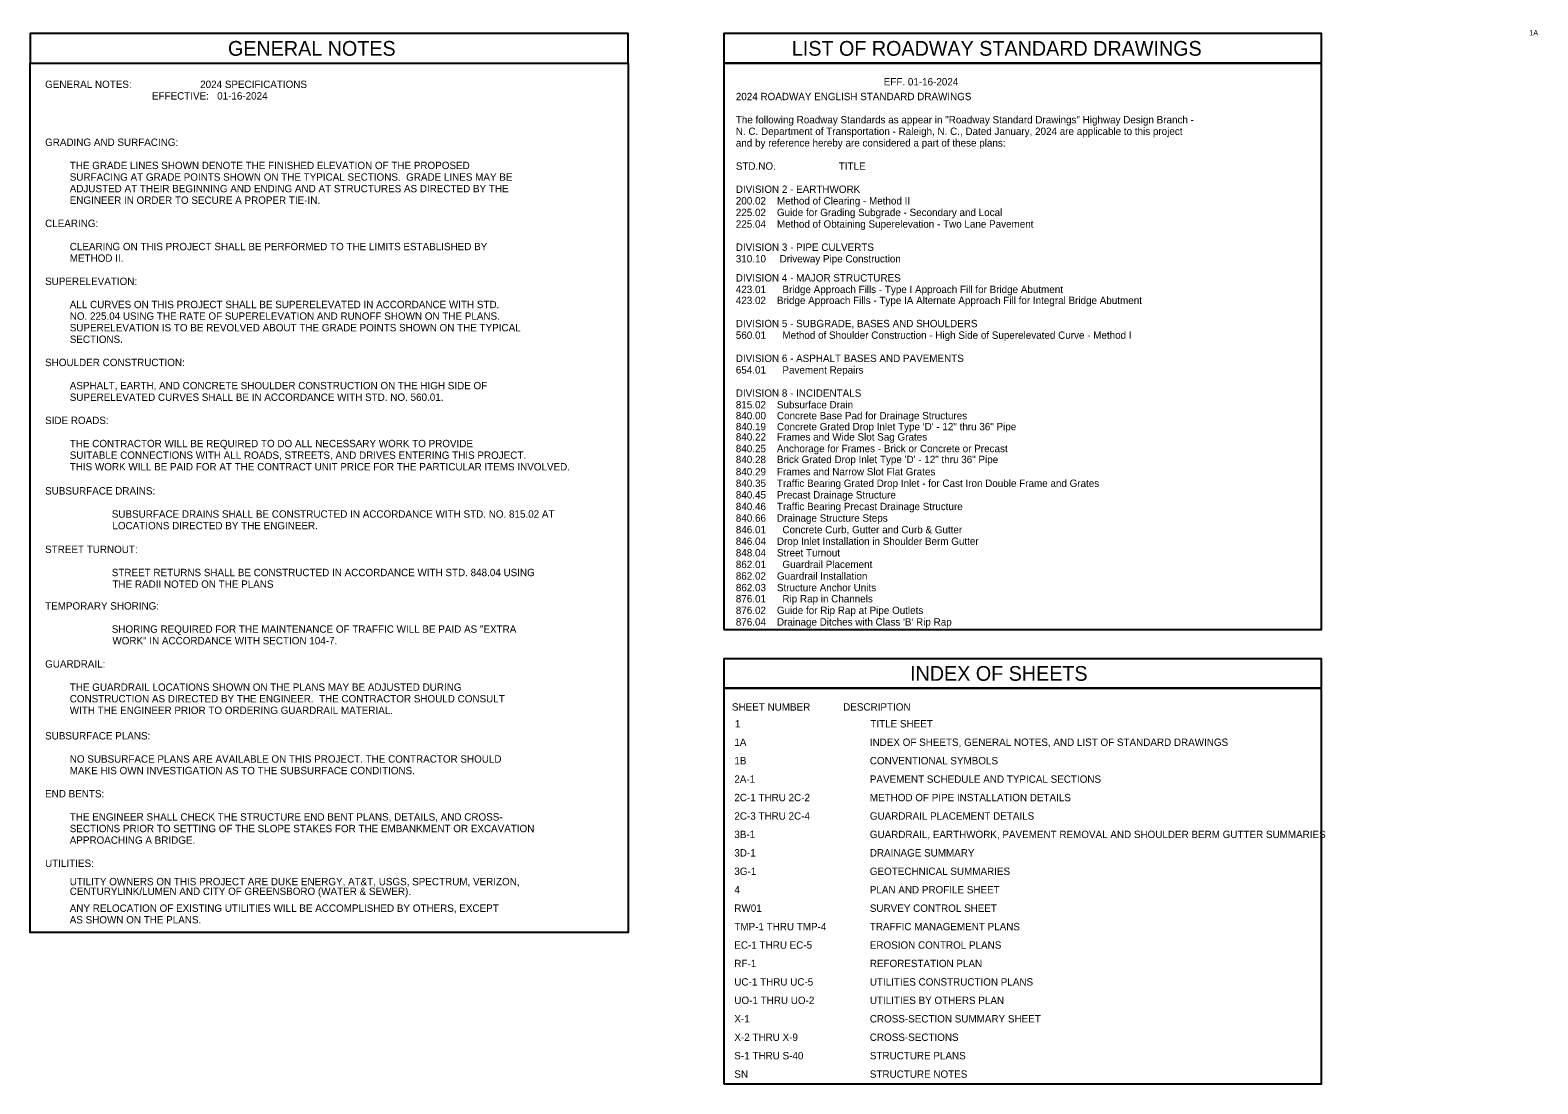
# Model space of a CAD drawing. Extents: x 1364250 to 1365681, y 623147 to 624147.
import ezdxf

# ---------------------------------------------------------------- set-up
doc = ezdxf.new("R2010")
doc.units = 0
for name, color, linetype in [('Old_Level_1', 7, 'Continuous'), ('Old_Level_40', 7, 'Continuous'), ('Old_Level_44', 7, 'Continuous')]:
    doc.layers.add(name, color=color, linetype=linetype)

msp = doc.modelspace()

# ---------------------------------------------------------------- linework, layer by layer
at = {"layer": 'Old_Level_1'}
for points in [[(1364249.5, 624116.2), (1364817.1, 624116.2), (1364817.1, 623290.9), (1364249.5, 623290.9)], [(1364907.9, 623578.6), (1365475.5, 623578.6), (1365475.5, 624116.2), (1364907.9, 624116.2)], [(1364907.9, 623147.3), (1365475.5, 623147.3), (1365475.5, 623522.9), (1364907.9, 623522.9)]]:
    msp.add_lwpolyline(points, close=True, dxfattribs=at)
at = {"layer": 'Old_Level_40'}
for points in [[(1364249.5, 624116.2), (1364817.1, 624116.2), (1364817.1, 624144.2), (1364249.5, 624144.2)], [(1364907.9, 624116.2), (1365475.5, 624116.2), (1365475.5, 624144.2), (1364907.9, 624144.2)], [(1364907.9, 623522.9), (1365475.5, 623522.9), (1365475.5, 623550.9), (1364907.9, 623550.9)]]:
    msp.add_lwpolyline(points, close=True, dxfattribs=at)

# ---------------------------------------------------------------- texts
at = {"layer": 'Old_Level_1'}
for s, p in [('                                                      EFF. 01-16-2024', (1364919.4, 624095)), ('GENERAL NOTES:                         2024 SPECIFICATIONS', (1364263.7, 624092.6)), ('GENERAL NOTES:                         2024 SPECIFICATIONS', (1364263.7, 624092.6)), ('                                       EFFECTIVE:   01-16-2024', (1364263.7, 624081.6)), ('2024 ROADWAY ENGLISH STANDARD DRAWINGS', (1364919.4, 624081)), ('The following Roadway Standards as appear in "Roadway Standard Drawings" Highway Design Branch -', (1364919.4, 624059)), ('GRADING AND SURFACING:  ', (1364263.7, 624037.6)), ('and by reference hereby are considered a part of these plans:', (1364919.4, 624037)), ('N. C. Department of Transportation - Raleigh, N. C., Dated January, 2024 are applicable to this project', (1364919.4, 624048)), ('         THE GRADE LINES SHOWN DENOTE THE FINISHED ELEVATION OF THE PROPOSED ', (1364263.7, 624015.6)), ('STD.NO.                       TITLE', (1364919.4, 624015)), ('         SURFACING AT GRADE POINTS SHOWN ON THE TYPICAL SECTIONS.  GRADE LINES MAY BE ', (1364263.7, 624004.6)), ('         ADJUSTED AT THEIR BEGINNING AND ENDING AND AT STRUCTURES AS DIRECTED BY THE ', (1364263.7, 623993.6)), ('         ENGINEER IN ORDER TO SECURE A PROPER TIE-IN.  ', (1364263.7, 623982.6)), ('200.02    Method of Clearing - Method II', (1364919.4, 623982)), ('DIVISION 2 - EARTHWORK', (1364919.4, 623993)), ('225.02    Guide for Grading Subgrade - Secondary and Local', (1364919.4, 623971)), ('CLEARING:  ', (1364263.7, 623960.6)), ('225.04    Method of Obtaining Superelevation - Two Lane Pavement', (1364919.4, 623960)), ('         CLEARING ON THIS PROJECT SHALL BE PERFORMED TO THE LIMITS ESTABLISHED BY ', (1364263.7, 623938.6)), ('DIVISION 3 - PIPE CULVERTS', (1364919.4, 623938)), ('         METHOD II.', (1364263.7, 623927.6)), ('310.10     Driveway Pipe Construction', (1364919.4, 623927)), ('DIVISION 4 - MAJOR STRUCTURES', (1364919.4, 623908.9)), ('SUPERELEVATION:  ', (1364263.7, 623905.6)), ('423.01      Bridge Approach Fills - Type I Approach Fill for Bridge Abutment', (1364919.4, 623897.9)), ('         ALL CURVES ON THIS PROJECT SHALL BE SUPERELEVATED IN ACCORDANCE WITH STD. ', (1364263.7, 623883.6)), ('423.02    Bridge Approach Fills - Type IA Alternate Approach Fill for Integral Bridge Abutment', (1364919.4, 623887.5)), ('         NO. 225.04 USING THE RATE OF SUPERELEVATION AND RUNOFF SHOWN ON THE PLANS.', (1364263.7, 623872.6)), ('DIVISION 5 - SUBGRADE, BASES AND SHOULDERS', (1364919.4, 623865.5)), ('         SUPERELEVATION IS TO BE REVOLVED ABOUT THE GRADE POINTS SHOWN ON THE TYPICAL ', (1364263.7, 623861.6)), ('560.01      Method of Shoulder Construction - High Side of Superelevated Curve - Method I', (1364919.4, 623854.5)), ('         SECTIONS.  ', (1364263.7, 623850.6)), ('SHOULDER CONSTRUCTION:  ', (1364263.7, 623828.6)), ('DIVISION 6 - ASPHALT BASES AND PAVEMENTS', (1364919.4, 623832.5)), ('654.01      Pavement Repairs', (1364919.4, 623821.5)), ('         ASPHALT, EARTH, AND CONCRETE SHOULDER CONSTRUCTION ON THE HIGH SIDE OF', (1364263.7, 623806.6)), ('         SUPERELEVATED CURVES SHALL BE IN ACCORDANCE WITH STD. NO. 560.01.', (1364263.7, 623795.6)), ('DIVISION 8 - INCIDENTALS', (1364919.4, 623799.5)), ('815.02    Subsurface Drain', (1364919.4, 623788.5)), ('SIDE ROADS:', (1364263.7, 623773.6)), ('840.00    Concrete Base Pad for Drainage Structures', (1364919.4, 623778.1)), ('840.19    Concrete Grated Drop Inlet Type \'D\' - 12" thru 36" Pipe', (1364919.4, 623767.7)), ('         THE CONTRACTOR WILL BE REQUIRED TO DO ALL NECESSARY WORK TO PROVIDE ', (1364263.7, 623751.6)), ('840.22    Frames and Wide Slot Sag Grates', (1364919.4, 623757.9)), ('         SUITABLE CONNECTIONS WITH ALL ROADS, STREETS, AND DRIVES ENTERING THIS PROJECT.', (1364263.7, 623740.6)), ('840.25    Anchorage for Frames - Brick or Concrete or Precast', (1364919.4, 623746.9)), ('840.28    Brick Grated Drop Inlet Type \'D\' - 12" thru 36" Pipe', (1364919.4, 623736.5)), ('         THIS WORK WILL BE PAID FOR AT THE CONTRACT UNIT PRICE FOR THE PARTICULAR ITEMS INVOLVED.', (1364263.7, 623729.6)), ('840.29    Frames and Narrow Slot Flat Grates', (1364919.4, 623724.9)), ('840.35    Traffic Bearing Grated Drop Inlet - for Cast Iron Double Frame and Grates', (1364919.4, 623713.9)), ('SUBSURFACE DRAINS:', (1364263.7, 623706.7)), ('840.45    Precast Drainage Structure', (1364919.4, 623702.9)), ('SUBSURFACE DRAINS SHALL BE CONSTRUCTED IN ACCORDANCE WITH STD. NO. 815.02 AT', (1364327, 623684.7)), ('840.46    Traffic Bearing Precast Drainage Structure', (1364919.4, 623691.9)), ('840.66    Drainage Structure Steps', (1364919.4, 623680.9)), ('LOCATIONS DIRECTED BY THE ENGINEER.', (1364327.6, 623673.7)), ('846.01      Concrete Curb, Gutter and Curb & Gutter', (1364919.4, 623669.9)), ('STREET TURNOUT:', (1364263.7, 623651.2)), ('846.04    Drop Inlet Installation in Shoulder Berm Gutter', (1364919.4, 623658.9)), ('848.04    Street Turnout', (1364919.4, 623647.9)), ('862.01      Guardrail Placement', (1364919.4, 623636.9)), ('STREET RETURNS SHALL BE CONSTRUCTED IN ACCORDANCE WITH STD. 848.04 USING', (1364327, 623629.2)), ('862.02    Guardrail Installation', (1364919.4, 623625.9)), ('THE RADII NOTED ON THE PLANS', (1364327.6, 623618.2)), ('862.03    Structure Anchor Units', (1364919.4, 623614.9)), ('TEMPORARY SHORING:', (1364263.7, 623597.5)), ('876.01      Rip Rap in Channels', (1364919.4, 623604.3)), ('876.02    Guide for Rip Rap at Pipe Outlets', (1364919.4, 623593.3)), ("876.04    Drainage Ditches with Class 'B' Rip Rap", (1364919.4, 623582.3)), ('SHORING REQUIRED FOR THE MAINTENANCE OF TRAFFIC WILL BE PAID AS "EXTRA', (1364327, 623575.5)), ('WORK" IN ACCORDANCE WITH SECTION 104-7.', (1364327.6, 623564.5)), ('GUARDRAIL:  ', (1364263.7, 623542.4)), ('         THE GUARDRAIL LOCATIONS SHOWN ON THE PLANS MAY BE ADJUSTED DURING ', (1364263.7, 623520.4)), ('         CONSTRUCTION AS DIRECTED BY THE ENGINEER.  THE CONTRACTOR SHOULD CONSULT', (1364263.7, 623509.4)), ('         WITH THE ENGINEER PRIOR TO ORDERING GUARDRAIL MATERIAL.', (1364263.7, 623498.4)), ('SHEET NUMBER            DESCRIPTION', (1364915.7, 623501.6)), ('1 ', (1364918.5, 623485.6)), ('TITLE SHEET', (1365047.1, 623485.6)), ('SUBSURFACE PLANS:', (1364263.7, 623474.2)), ('1A ', (1364918, 623468.1)), ('INDEX OF SHEETS, GENERAL NOTES, AND LIST OF STANDARD DRAWINGS', (1365046.6, 623468.1)), ('         NO SUBSURFACE PLANS ARE AVAILABLE ON THIS PROJECT. THE CONTRACTOR SHOULD', (1364263.7, 623452.2)), ('1B  ', (1364918, 623450.6)), ('CONVENTIONAL SYMBOLS ', (1365046.6, 623450.6)), ('         MAKE HIS OWN INVESTIGATION AS TO THE SUBSURFACE CONDITIONS.', (1364263.7, 623441.2)), ('2A-1', (1364918, 623433.1)), ('PAVEMENT SCHEDULE AND TYPICAL SECTIONS', (1365046.6, 623433.1)), ('END BENTS:  ', (1364263.7, 623419.2)), ('2C-1 THRU 2C-2', (1364918, 623415.6)), ('METHOD OF PIPE INSTALLATION DETAILS', (1365046.6, 623415.6)), ('         THE ENGINEER SHALL CHECK THE STRUCTURE END BENT PLANS, DETAILS, AND CROSS-', (1364263.7, 623397.2)), ('2C-3 THRU 2C-4', (1364918, 623398.1)), ('GUARDRAIL PLACEMENT DETAILS', (1365046.6, 623398.1)), ('         SECTIONS PRIOR TO SETTING OF THE SLOPE STAKES FOR THE EMBANKMENT OR EXCAVATION ', (1364263.7, 623386.2)), ('3B-1     ', (1364918, 623380.6)), ('GUARDRAIL, EARTHWORK, PAVEMENT REMOVAL AND SHOULDER BERM GUTTER SUMMARIES', (1365046.6, 623380.6)), ('         APPROACHING A BRIDGE.  ', (1364263.7, 623375.2)), ('UTILITIES:  ', (1364263.7, 623353.2)), ('3D-1     ', (1364918, 623363.1)), ('DRAINAGE SUMMARY', (1365046.6, 623363.1)), ('         UTILITY OWNERS ON THIS PROJECT ARE DUKE ENERGY, AT&T, USGS, SPECTRUM, VERIZON,', (1364263.7, 623335.8)), ('3G-1     ', (1364918, 623345.6)), ('GEOTECHNICAL SUMMARIES', (1365046.6, 623345.6)), ('         CENTURYLINK/LUMEN AND CITY OF GREENSBORO (WATER & SEWER).', (1364263.7, 623326.6)), ('4    ', (1364918, 623328.1)), ('PLAN AND PROFILE SHEET', (1365046.6, 623328.1)), ('         ANY RELOCATION OF EXISTING UTILITIES WILL BE ACCOMPLISHED BY OTHERS, EXCEPT', (1364263.7, 623310.6)), ('RW01', (1364918, 623310.6)), ('SURVEY CONTROL SHEET', (1365046.6, 623310.6)), ('         AS SHOWN ON THE PLANS.  ', (1364263.7, 623299.6)), ('TMP-1 THRU TMP-4    ', (1364918, 623293.1)), ('TRAFFIC MANAGEMENT PLANS', (1365046.6, 623293.1)), ('EC-1 THRU EC-5     ', (1364918, 623275.6)), ('EROSION CONTROL PLANS', (1365046.6, 623275.6)), ('RF-1    ', (1364918, 623258.1)), ('REFORESTATION PLAN', (1365046.6, 623258.1)), ('UC-1 THRU UC-5  ', (1364918, 623240.6)), ('UTILITIES CONSTRUCTION PLANS', (1365046.6, 623240.6)), ('UO-1 THRU UO-2    ', (1364918, 623223.1)), ('UTILITIES BY OTHERS PLAN', (1365046.6, 623223.1)), ('X-1', (1364918, 623205.6)), ('CROSS-SECTION SUMMARY SHEET', (1365046.6, 623205.6)), ('X-2 THRU X-9', (1364918, 623188.1)), ('CROSS-SECTIONS', (1365046.6, 623188.1)), ('S-1 THRU S-40', (1364918, 623170.6)), ('STRUCTURE PLANS', (1365046.6, 623170.6)), ('SN ', (1364918, 623153.1)), ('STRUCTURE NOTES', (1365046.6, 623153.1))]:
    msp.add_text(s, height=7, dxfattribs=at).set_placement(p)
at = {"layer": 'Old_Level_40'}
for s, p in [('GENERAL NOTES', (1364437.3, 624123.2)), ('LIST OF ROADWAY STANDARD DRAWINGS', (1364972.6, 624123.2)), ('INDEX OF SHEETS', (1365084.8, 623529.9))]:
    msp.add_text(s, height=14, dxfattribs=at).set_placement(p)
at = {"layer": 'Old_Level_44'}
msp.add_text('1A', height=5, dxfattribs=at).set_placement((1365672.6, 624142.5))

doc.saveas('drawing.dxf')
